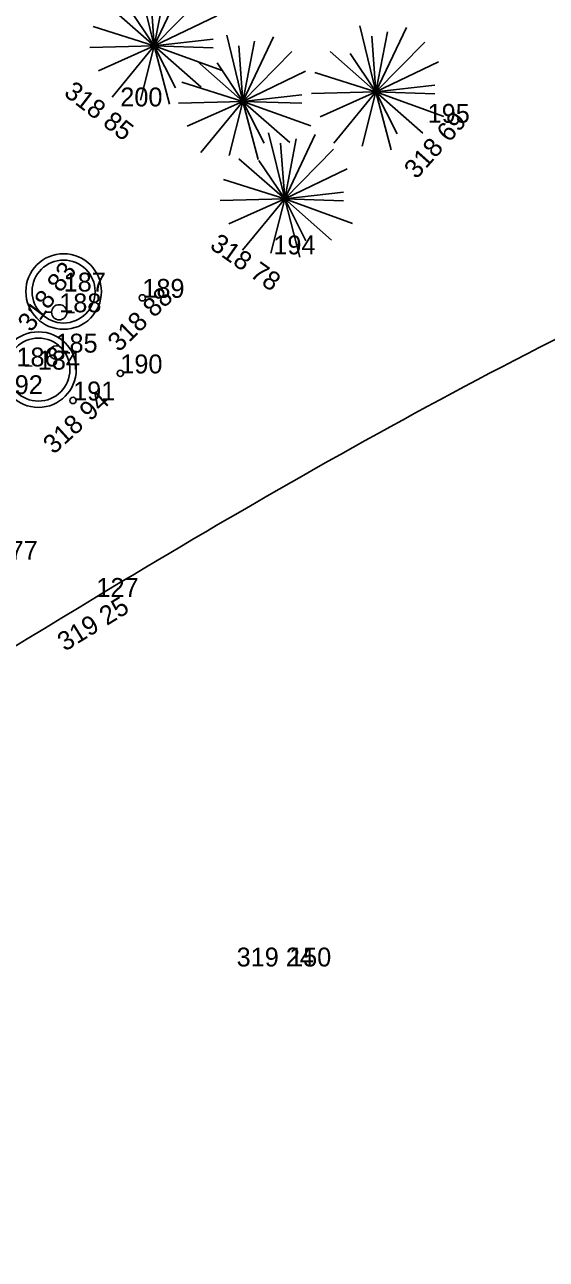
# Model space of a CAD drawing. Extents: x -742884 to -742543, y -1054677 to -1054433.
# Drawn here: x -742737.91 to -742729.63, y -1054520.62 to -1054501.01 of the extents above; entities that cross this region are included whole.
import ezdxf

# ---------------------------------------------------------------- set-up
doc = ezdxf.new("R2010")
doc.units = 0
for name, color, linetype in [('Vrstva 1', 7, 'Continuous'), ('Vrstva 10', 7, 'Continuous'), ('Vrstva 11', 7, 'Continuous'), ('Vrstva 2', 7, 'Continuous'), ('Vrstva 3', 7, 'Continuous'), ('Vrstva 4', 7, 'Continuous'), ('Vrstva 8', 7, 'Continuous')]:
    doc.layers.add(name, color=color, linetype=linetype)

msp = doc.modelspace()

# ---------------------------------------------------------------- linework, layer by layer
at = {"layer": 'Vrstva 1'}
for p, q in [((-742736.39, -1054502.31), (-742736.39, -1054502.31)), ((-742731.51, -1054502.57), (-742731.51, -1054502.57)), ((-742733.96, -1054504.66), (-742733.96, -1054504.66)), ((-742737.29, -1054505.25), (-742737.29, -1054505.25)), ((-742736.04, -1054505.35), (-742736.04, -1054505.35)), ((-742737.36, -1054505.58), (-742737.36, -1054505.58)), ((-742737.42, -1054506.22), (-742737.42, -1054506.22)), ((-742737.7, -1054506.49), (-742737.7, -1054506.49)), ((-742736.39, -1054506.55), (-742736.39, -1054506.55)), ((-742737.14, -1054506.98), (-742737.14, -1054506.98)), ((-742736.77, -1054510.1), (-742736.77, -1054510.1)), ((-742733.71, -1054515.97), (-742733.71, -1054515.97))]:
    msp.add_line(p, q, dxfattribs=at)
at = {"layer": 'Vrstva 10'}
for p, q in [((-742735.85, -1054501.35), (-742736.107, -1054500.3)), ((-742735.85, -1054501.35), (-742735.914, -1054500.466)), ((-742735.85, -1054501.35), (-742735.365, -1054500.325)), ((-742735.85, -1054501.35), (-742735.666, -1054500.394)), ((-742735.85, -1054501.35), (-742735.077, -1054500.559)), ((-742735.85, -1054501.35), (-742736.579, -1054500.71)), ((-742735.85, -1054501.35), (-742736.26, -1054500.739)), ((-742735.85, -1054501.35), (-742734.858, -1054500.871)), ((-742735.85, -1054501.35), (-742736.819, -1054501.043)), ((-742732.33, -1054502.08), (-742732.587, -1054501.03)), ((-742732.33, -1054502.08), (-742731.845, -1054501.055)), ((-742735.85, -1054501.35), (-742734.918, -1054501.244)), ((-742734.442, -1054502.23), (-742734.699, -1054501.18)), ((-742734.442, -1054502.23), (-742733.957, -1054501.205)), ((-742732.33, -1054502.08), (-742732.394, -1054501.196)), ((-742732.33, -1054502.08), (-742732.146, -1054501.124)), ((-742735.85, -1054501.35), (-742736.872, -1054501.376)), ((-742735.85, -1054501.35), (-742736.735, -1054501.743)), ((-742735.85, -1054501.35), (-742736.52, -1054502.164)), ((-742735.85, -1054501.35), (-742736.07, -1054502.209)), ((-742735.854, -1054501.344), (-742735.854, -1054501.344)), ((-742735.85, -1054501.35), (-742735.85, -1054501.35)), ((-742735.85, -1054501.35), (-742735.514, -1054502.014)), ((-742735.85, -1054501.35), (-742734.775, -1054501.739)), ((-742735.85, -1054501.35), (-742734.918, -1054501.378)), ((-742735.85, -1054501.35), (-742735.104, -1054502.003)), ((-742735.85, -1054501.35), (-742735.61, -1054502.272)), ((-742735.85, -1054501.35), (-742735.85, -1054501.35)), ((-742734.442, -1054502.23), (-742734.506, -1054501.346)), ((-742734.442, -1054502.23), (-742734.258, -1054501.274)), ((-742734.442, -1054502.23), (-742733.669, -1054501.439)), ((-742732.33, -1054502.08), (-742733.059, -1054501.44)), ((-742732.33, -1054502.08), (-742731.557, -1054501.289)), ((-742734.442, -1054502.23), (-742735.171, -1054501.59)), ((-742734.442, -1054502.23), (-742734.852, -1054501.619)), ((-742732.33, -1054502.08), (-742732.74, -1054501.469)), ((-742732.33, -1054502.08), (-742731.338, -1054501.601)), ((-742734.442, -1054502.23), (-742733.45, -1054501.751)), ((-742732.33, -1054502.08), (-742733.299, -1054501.773)), ((-742734.442, -1054502.23), (-742735.411, -1054501.923)), ((-742732.33, -1054502.08), (-742731.398, -1054501.974)), ((-742734.442, -1054502.23), (-742735.464, -1054502.256)), ((-742734.442, -1054502.23), (-742735.327, -1054502.623)), ((-742734.442, -1054502.23), (-742735.112, -1054503.044)), ((-742734.442, -1054502.23), (-742734.662, -1054503.089)), ((-742734.446, -1054502.224), (-742734.446, -1054502.224)), ((-742734.442, -1054502.23), (-742733.51, -1054502.124)), ((-742734.442, -1054502.23), (-742734.442, -1054502.23)), ((-742734.442, -1054502.23), (-742734.106, -1054502.894)), ((-742734.442, -1054502.23), (-742733.367, -1054502.619)), ((-742734.442, -1054502.23), (-742733.51, -1054502.258)), ((-742734.442, -1054502.23), (-742733.696, -1054502.883)), ((-742734.442, -1054502.23), (-742734.202, -1054503.152)), ((-742734.442, -1054502.23), (-742734.442, -1054502.23)), ((-742732.33, -1054502.08), (-742733.352, -1054502.106)), ((-742732.33, -1054502.08), (-742733.215, -1054502.473)), ((-742732.33, -1054502.08), (-742733, -1054502.894)), ((-742732.33, -1054502.08), (-742732.55, -1054502.939)), ((-742732.334, -1054502.074), (-742732.334, -1054502.074)), ((-742732.33, -1054502.08), (-742732.33, -1054502.08)), ((-742732.33, -1054502.08), (-742731.994, -1054502.744)), ((-742732.33, -1054502.08), (-742731.255, -1054502.469)), ((-742732.33, -1054502.08), (-742731.398, -1054502.108)), ((-742732.33, -1054502.08), (-742731.584, -1054502.733)), ((-742732.33, -1054502.08), (-742732.09, -1054503.002)), ((-742732.33, -1054502.08), (-742732.33, -1054502.08)), ((-742733.78, -1054503.78), (-742734.037, -1054502.73)), ((-742733.78, -1054503.78), (-742733.295, -1054502.755)), ((-742733.78, -1054503.78), (-742733.596, -1054502.824)), ((-742733.78, -1054503.78), (-742733.844, -1054502.896)), ((-742733.78, -1054503.78), (-742733.007, -1054502.989)), ((-742733.78, -1054503.78), (-742734.509, -1054503.14)), ((-742733.78, -1054503.78), (-742734.19, -1054503.169)), ((-742733.78, -1054503.78), (-742732.788, -1054503.301)), ((-742733.78, -1054503.78), (-742734.749, -1054503.473)), ((-742733.78, -1054503.78), (-742734.802, -1054503.806)), ((-742733.78, -1054503.78), (-742734.665, -1054504.173)), ((-742733.78, -1054503.78), (-742734.45, -1054504.594)), ((-742733.78, -1054503.78), (-742734, -1054504.639)), ((-742733.784, -1054503.774), (-742733.784, -1054503.774)), ((-742733.78, -1054503.78), (-742732.848, -1054503.674)), ((-742733.78, -1054503.78), (-742733.78, -1054503.78)), ((-742733.78, -1054503.78), (-742733.444, -1054504.444)), ((-742733.78, -1054503.78), (-742732.705, -1054504.169)), ((-742733.78, -1054503.78), (-742732.848, -1054503.808)), ((-742733.78, -1054503.78), (-742733.034, -1054504.433)), ((-742733.78, -1054503.78), (-742733.54, -1054504.702)), ((-742733.78, -1054503.78), (-742733.78, -1054503.78))]:
    msp.add_line(p, q, dxfattribs=at)
at = {"layer": 'Vrstva 11'}
for points in [[(-742777.63, -1054542.12), (-742764.61, -1054526.83), (-742751.7, -1054511.56), (-742738.47, -1054495.82), (-742727.02, -1054482.18), (-742726.38, -1054482.19), (-742725.15, -1054482.94)], [(-742776.7, -1054542.68), (-742764.01, -1054527.79), (-742751.11, -1054512.75), (-742737.61, -1054496.47), (-742726.42, -1054483.98), (-742725.9, -1054484.03), (-742714, -1054491.86), (-742704.819, -1054497.481), (-742700.94, -1054500.269), (-742696.44, -1054503.39), (-742688.83, -1054509.5), (-742682.54, -1054514.17), (-742675.15, -1054519.77), (-742673.01, -1054522.11), (-742671.05, -1054524.7)], [(-742641.45, -1054542), (-742646.08, -1054542.32), (-742650.28, -1054545.1), (-742653.63, -1054549.14), (-742658.66, -1054557.13), (-742664.13, -1054565.84), (-742667.81, -1054569.62), (-742669.76, -1054570.07), (-742674.4, -1054567.88), (-742684.66, -1054562.03), (-742693.02, -1054556.88), (-742694.43, -1054554.37), (-742693.99, -1054552.67), (-742684.52, -1054539.64), (-742677.51, -1054529.95), (-742676.26, -1054526.54), (-742677.27, -1054522.39), (-742681.19, -1054517.29), (-742689.28, -1054510.73), (-742697.86, -1054505.14), (-742704.02, -1054502.75), (-742713.11, -1054501.07), (-742723.98, -1054503.51), (-742736.77, -1054510.1), (-742745.39, -1054515.75), (-742752.81, -1054521.82), (-742762.72, -1054531.38), (-742770.54, -1054539.36), (-742775.54, -1054544.64)]]:
    msp.add_spline(points, degree=3, dxfattribs=at)
at = {"layer": 'Vrstva 4'}
for points in [[(-742783.23, -1054536.93), (-742770.7, -1054522.44), (-742757.28, -1054506.67), (-742744.15, -1054491.3), (-742731.95, -1054477.03), (-742724.73, -1054468.59)], [(-742778.49, -1054541.37), (-742765.63, -1054526.43), (-742752.39, -1054510.77), (-742739.19, -1054495.37), (-742727.3, -1054481.14)]]:
    msp.add_spline(points, degree=3, dxfattribs=at)
at = {"layer": 'Vrstva 8'}
for p, q in [((-742737.481, -1054505.579), (-742737.596, -1054505.577)), ((-742737.12, -1054505.583), (-742737.238, -1054505.582)), ((-742737.514, -1054506.219), (-742737.617, -1054506.217)), ((-742737.189, -1054506.223), (-742737.295, -1054506.222)), ((-742737.79, -1054506.433), (-742737.908, -1054506.432))]:
    msp.add_line(p, q, dxfattribs=at)
for centre, radius in [((-742737.29, -1054505.25), 0.6), ((-742737.29, -1054505.25), 0.5), ((-742736.04, -1054505.35), 0.05), ((-742737.36, -1054505.58), 0.121), ((-742737.69, -1054506.49), 0.6), ((-742737.69, -1054506.49), 0.5), ((-742737.405, -1054506.22), 0.109), ((-742736.39, -1054506.55), 0.05), ((-742737.14, -1054506.98), 0.05)]:
    msp.add_circle(centre, radius, dxfattribs=at)

# ---------------------------------------------------------------- texts
at = {"layer": 'Vrstva 2'}
for s, p in [('200', (-742736.39, -1054502.31)), ('195', (-742731.51, -1054502.57)), ('194', (-742733.96, -1054504.66)), ('187', (-742737.29, -1054505.25)), ('189', (-742736.04, -1054505.35)), ('188', (-742737.36, -1054505.58)), ('185', (-742737.42, -1054506.22)), ('186', (-742738.04, -1054506.44)), ('184', (-742737.7, -1054506.49)), ('190', (-742736.39, -1054506.55)), ('192', (-742738.29, -1054506.88)), ('191', (-742737.14, -1054506.98)), ('177', (-742738.37, -1054509.51)), ('127', (-742736.77, -1054510.1)), ('150', (-742733.71, -1054515.97))]:
    msp.add_text(s, height=0.3, dxfattribs=at).set_placement(p)
at = {"layer": 'Vrstva 3'}
for s, rotation, p in [('318 85 ', 322.36, (-742737.303, -1054502.124)), ('318 69 ', 48.3339, (-742731.688, -1054503.477)), ('318 78 ', 324.8221, (-742734.986, -1054504.553)), ('318 83 ', 53.3787, (-742737.803, -1054505.908)), ('318 88 ', 44.3377, (-742736.412, -1054506.223)), ('318 94 ', 42.3493, (-742737.447, -1054507.847)), ('319 25 ', 31.6466, (-742737.269, -1054510.973))]:
    msp.add_text(s, height=0.3, rotation=rotation, dxfattribs=at).set_placement(p)
msp.add_text('319 24 ', height=0.3, dxfattribs=at).set_placement((-742734.543, -1054515.97))

doc.saveas('drawing.dxf')
